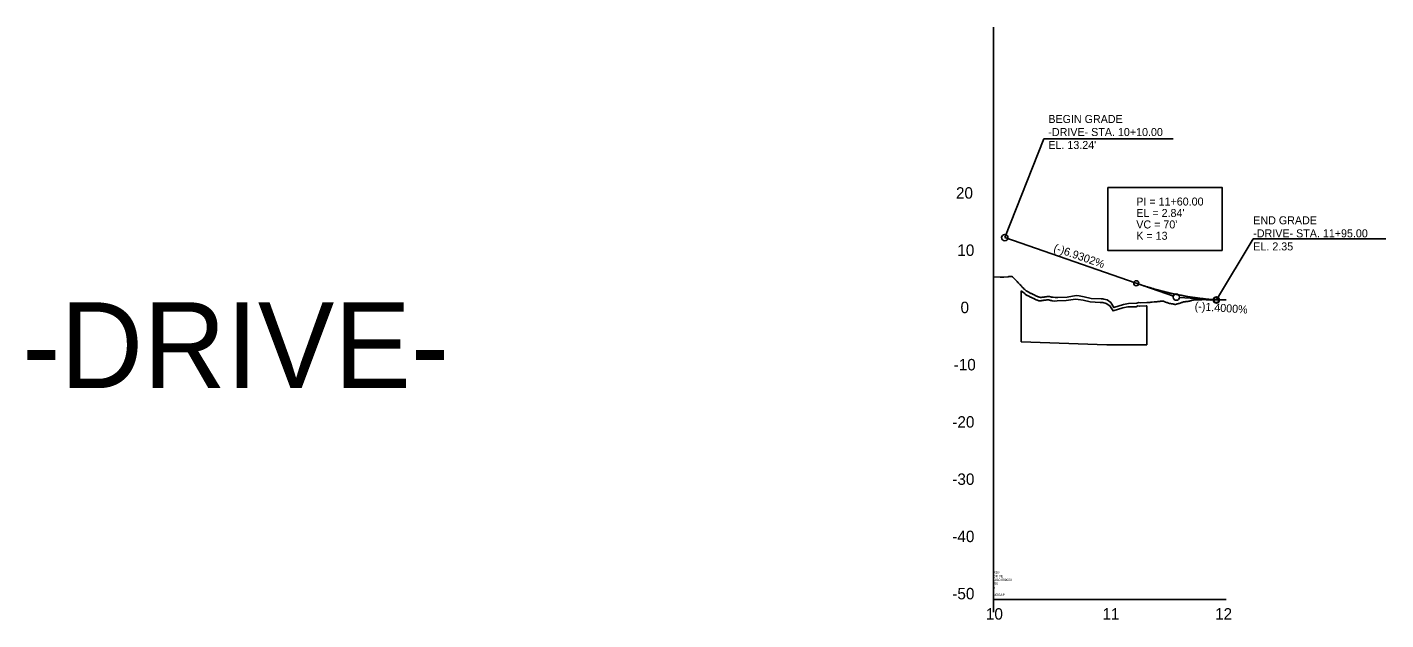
# Model space of a CAD drawing. Extents: x 1626634 to 1638383, y 876896 to 886347.
# Drawn here: x 1631869 to 1633057, y 882819 to 883336 of the extents above; entities that cross this region are included whole.
import ezdxf

# ---------------------------------------------------------------- set-up
doc = ezdxf.new("R2010")
doc.units = 0
for name, color, linetype in [('DTM Contours Minor', 7, 'Continuous'), ('Exist Profile Cell', 7, 'Continuous'), ('Exist Vertical Profile Ground Line', 7, 'Continuous'), ('Exist Vertical Profile Horizontal Axis Label Major', 7, 'Continuous'), ('Exist Vertical Profile Vertical Axis Label', 7, 'Continuous'), ('Prop Vertical Profile Curve Label', 7, 'Continuous'), ('Prop Vertical Profile Grade', 7, 'Continuous'), ('Prop Vertical Profile Grade Label', 7, 'Continuous'), ('Prop VPI Label', 7, 'Continuous'), ('Scratch_Level_3', 7, 'Continuous')]:
    doc.layers.add(name, color=color, linetype=linetype)

msp = doc.modelspace()

# ---------------------------------------------------------------- linework, layer by layer
at = {"layer": 'DTM Contours Minor'}
msp.add_line((1632713.9, 882825.5), (1632713.9, 882971.1), dxfattribs=at)
at = {"layer": 'Exist Profile Cell'}
for q in [(1632713.9, 883336.5), (1632917.4, 882836.5), (1632713.9, 882836.5)]:
    msp.add_line((1632713.9, 882836.5), q, dxfattribs=at)
at = {"layer": 'Exist Vertical Profile Ground Line'}
msp.add_lwpolyline([(1632713.9, 883118.3), (1632720, 883118.1), (1632723, 883118.1), (1632726.8, 883118.5), (1632727.3, 883118.6), (1632727.8, 883118.6), (1632728.3, 883118.7), (1632728.7, 883118.7), (1632729.2, 883118.8), (1632730.2, 883118.7), (1632730.7, 883118.3), (1632731.2, 883117.9), (1632731.7, 883117.4), (1632732.1, 883117), (1632732.7, 883116.5), (1632733.1, 883116.1), (1632733.6, 883115.5), (1632734.1, 883115), (1632734.6, 883114.4), (1632735.1, 883113.9), (1632735.5, 883113.4), (1632736, 883112.8), (1632736.5, 883112.3), (1632737, 883111.8), (1632737.5, 883111.3), (1632738, 883110.8), (1632738.5, 883110.2), (1632738.9, 883109.7), (1632739.4, 883109.2), (1632739.9, 883108.7), (1632740.9, 883107.7), (1632741.4, 883107.4), (1632741.8, 883107.1), (1632742.3, 883106.6), (1632742.7, 883106.1), (1632743.3, 883105.8), (1632743.8, 883105.5), (1632744.3, 883105.2), (1632744.8, 883105), (1632745.2, 883104.7), (1632745.7, 883104.5), (1632746.2, 883104.3), (1632746.7, 883104), (1632747.2, 883103.8), (1632747.7, 883103.6), (1632748.2, 883103.3), (1632748.7, 883103.1), (1632749.1, 883102.9), (1632749.6, 883102.6), (1632750.1, 883102.4), (1632750.6, 883102.1), (1632751.1, 883101.9), (1632751.6, 883101.6), (1632752, 883101.4), (1632753, 883101), (1632753.5, 883100.9), (1632754, 883100.7), (1632754.5, 883100.6), (1632755, 883100.5), (1632755.5, 883100.4), (1632755.9, 883100.5), (1632756.4, 883100.6), (1632757, 883100.7), (1632757.4, 883100.8), (1632757.9, 883100.8), (1632758.4, 883100.8), (1632758.8, 883100.9), (1632759.3, 883100.9), (1632759.8, 883101), (1632760.3, 883101), (1632760.8, 883101.1), (1632761.3, 883101.1), (1632761.8, 883101.2), (1632762.7, 883101.3), (1632763.2, 883101.1), (1632763.7, 883101), (1632764.2, 883100.9), (1632764.7, 883100.8), (1632765.2, 883100.7), (1632765.6, 883100.7), (1632766.1, 883100.6), (1632768, 883100.3), (1632770.4, 883100.4), (1632778.4, 883100.8), (1632786.4, 883102), (1632788.8, 883101.7), (1632793.3, 883101), (1632799.3, 883099.6), (1632808.2, 883099.1), (1632809.7, 883099.1), (1632810.5, 883098.9), (1632813.3, 883098.2), (1632816.6, 883096), (1632819.4, 883091.6), (1632827.8, 883094.2), (1632832.2, 883095.1), (1632839.5, 883095.3), (1632841, 883096), (1632842.7, 883095.7), (1632848.2, 883096), (1632850.7, 883096), (1632851.5, 883096.2), (1632852.9, 883096.3), (1632854.5, 883096.5), (1632855.1, 883096.5), (1632855.7, 883096.6), (1632856.4, 883096.6), (1632857, 883096.7), (1632857.6, 883096.8), (1632858.2, 883096.8), (1632858.9, 883096.9), (1632859.5, 883097), (1632860.1, 883097.1), (1632860.8, 883097.1), (1632861.4, 883097.2), (1632862.1, 883097.3), (1632862.7, 883097.1), (1632863.3, 883096.8), (1632863.9, 883096.6), (1632864.5, 883096.3), (1632865.2, 883096.1), (1632865.8, 883095.9), (1632866.4, 883095.7), (1632867.1, 883095.4), (1632867.8, 883095.2), (1632868.3, 883095.1), (1632868.9, 883095), (1632869.6, 883094.9), (1632870.2, 883094.8), (1632870.8, 883094.7), (1632871.5, 883094.6), (1632872.1, 883094.5), (1632872.7, 883094.4), (1632873.1, 883094.3), (1632874, 883094.6), (1632874.6, 883094.7), (1632875.2, 883094.9), (1632875.9, 883095.1), (1632876.5, 883095.2), (1632877.4, 883095.5), (1632877.8, 883095.6), (1632878.4, 883095.9), (1632879, 883096.1), (1632879.6, 883096.4), (1632880.3, 883096.6), (1632880.9, 883096.7), (1632881.5, 883096.7), (1632882.2, 883096.8), (1632882.8, 883096.8), (1632883.5, 883096.9), (1632884, 883097), (1632884.7, 883097.1), (1632885.3, 883097.2), (1632885.9, 883097.4), (1632886.6, 883097.6), (1632887.2, 883097.8), (1632887.8, 883098), (1632888.5, 883098.1), (1632889.1, 883098.2), (1632889.7, 883098.2), (1632890.3, 883098.2), (1632891, 883098.2), (1632891.6, 883098.3), (1632892.2, 883098.3), (1632892.9, 883098.3), (1632893.5, 883098.4), (1632894.1, 883098.4), (1632894.7, 883098.4), (1632895.4, 883098.4), (1632896, 883098.4), (1632896.6, 883098.5), (1632897.3, 883098.5), (1632897.9, 883098.5), (1632898.7, 883098.5), (1632899.1, 883098.5), (1632899.8, 883098.5), (1632900.4, 883098.4), (1632901, 883098.4), (1632901.7, 883098.3), (1632902.3, 883098.3), (1632902.9, 883098.2), (1632903.5, 883098.2), (1632904.4, 883098.1), (1632911.9, 883098.3), (1632917.4, 883098.2)], dxfattribs=at)
at = {"layer": 'Prop Vertical Profile Curve Label'}
for centre in [(1632838.9, 883112.8), (1632908.9, 883098.2)]:
    msp.add_circle(centre, 2.25, dxfattribs=at)
at = {"layer": 'Prop Vertical Profile Grade'}
msp.add_line((1632723.9, 883152.7), (1632838.9, 883112.8), dxfattribs=at)
msp.add_spline([(1632838.9, 883112.8), (1632840.3, 883112.3), (1632841.7, 883111.9), (1632843.1, 883111.4), (1632844.5, 883110.9), (1632845.9, 883110.5), (1632847.3, 883110), (1632848.7, 883109.6), (1632850.1, 883109.2), (1632851.5, 883108.8), (1632852.9, 883108.3), (1632854.3, 883107.9), (1632855.7, 883107.5), (1632857.1, 883107.2), (1632858.5, 883106.8), (1632859.9, 883106.4), (1632861.3, 883106), (1632862.7, 883105.7), (1632864.1, 883105.3), (1632865.5, 883105), (1632866.9, 883104.7), (1632868.3, 883104.3), (1632869.7, 883104), (1632871.1, 883103.7), (1632872.5, 883103.4), (1632873.9, 883103.1), (1632875.3, 883102.8), (1632876.7, 883102.5), (1632878.1, 883102.3), (1632879.5, 883102), (1632880.9, 883101.7), (1632882.3, 883101.5), (1632883.7, 883101.2), (1632885.1, 883101), (1632886.5, 883100.8), (1632887.9, 883100.6), (1632889.3, 883100.4), (1632890.7, 883100.2), (1632892.1, 883100), (1632893.5, 883099.8), (1632894.9, 883099.6), (1632896.3, 883099.4), (1632897.7, 883099.3), (1632899.1, 883099.1), (1632900.5, 883099), (1632901.9, 883098.8), (1632903.3, 883098.7), (1632904.7, 883098.6), (1632906.1, 883098.4), (1632907.5, 883098.3), (1632908.9, 883098.2)], degree=3, dxfattribs=at)
at = {"layer": 'Prop VPI Label'}
for p, q in [((1632723.9, 883152.7), (1632758.1, 883238.9)), ((1632871.2, 883238.9), (1632758.1, 883238.9)), ((1632908.9, 883098.2), (1632941.2, 883151.6)), ((1633057.1, 883151.6), (1632941.2, 883151.6)), ((1632838.9, 883112.8), (1632871.3, 883101.6)), ((1632908.9, 883098.2), (1632876.6, 883100.5))]:
    msp.add_line(p, q, dxfattribs=at)
msp.add_lwpolyline([(1632813.9, 883196.5), (1632913.9, 883196.5), (1632913.9, 883141.5), (1632813.9, 883141.5)], close=True, dxfattribs=at)
msp.add_lwpolyline([(1632813.9, 883196.5), (1632913.9, 883196.5), (1632913.9, 883141.5), (1632813.9, 883141.5)], close=True, dxfattribs=at)
for centre in [(1632723.9, 883152.7), (1632723.9, 883152.7), (1632873.9, 883100.7), (1632908.9, 883098.2)]:
    msp.add_circle(centre, 2.75, dxfattribs=at)
at = {"layer": 'Scratch_Level_3'}
for p, q in [((1632738.1, 883106.1), (1632738.1, 883061.5)), ((1632848.1, 883059), (1632848.1, 883093)), ((1632738.1, 883061.5), (1632813.1, 883059)), ((1632813.1, 883059), (1632848.1, 883059))]:
    msp.add_line(p, q, dxfattribs=at)
msp.add_lwpolyline([(1632738.1, 883106.1), (1632740.6, 883104.4), (1632741, 883104.1), (1632741.5, 883103.6), (1632741.9, 883103.1), (1632742.5, 883102.8), (1632743, 883102.5), (1632743.5, 883102.2), (1632744, 883102), (1632744.4, 883101.7), (1632744.9, 883101.5), (1632745.4, 883101.3), (1632745.9, 883101), (1632746.4, 883100.8), (1632746.9, 883100.6), (1632747.4, 883100.4), (1632747.9, 883100.1), (1632748.3, 883099.9), (1632748.8, 883099.6), (1632749.3, 883099.4), (1632749.8, 883099.1), (1632750.3, 883098.9), (1632750.8, 883098.7), (1632751.2, 883098.4), (1632752.2, 883098), (1632752.7, 883097.9), (1632753.2, 883097.8), (1632753.7, 883097.6), (1632754.2, 883097.5), (1632754.7, 883097.4), (1632755.1, 883097.5), (1632755.6, 883097.6), (1632756.2, 883097.7), (1632756.6, 883097.8), (1632757.1, 883097.8), (1632757.6, 883097.8), (1632758, 883097.9), (1632758.5, 883097.9), (1632759, 883098), (1632759.5, 883098), (1632760, 883098.1), (1632760.5, 883098.2), (1632761, 883098.2), (1632761.9, 883098.3), (1632762.4, 883098.2), (1632762.9, 883098), (1632763.4, 883097.9), (1632763.9, 883097.8), (1632764.4, 883097.7), (1632764.8, 883097.7), (1632765.3, 883097.6), (1632767.2, 883097.3), (1632769.6, 883097.4), (1632777.6, 883097.8), (1632785.6, 883099), (1632788, 883098.7), (1632792.5, 883098), (1632798.5, 883096.6), (1632807.4, 883096.1), (1632808.9, 883096.1), (1632809.7, 883095.9), (1632812.5, 883095.2), (1632815.8, 883093), (1632818.6, 883088.6), (1632827, 883091.2), (1632831.4, 883092.1), (1632838.7, 883092.3), (1632840.2, 883093), (1632841.9, 883092.7), (1632847.4, 883093), (1632848.1, 883093)], dxfattribs=at)

# ---------------------------------------------------------------- texts
at = {"layer": 'Exist Profile Cell'}
for s, p in [('RDY', (1632713.9, 882859.2)), ('DRIVE', (1632713.9, 882856)), ('-50', (1632713.9, 882849.5)), ('5', (1632713.9, 882846.2)), ('1000.000000', (1632713.9, 882852.7)), ('1', (1632713.9, 882843)), ('NOGAP', (1632713.9, 882839.7))]:
    msp.add_text(s, height=2, dxfattribs=at).set_placement(p)
at = {"layer": 'Exist Vertical Profile Horizontal Axis Label Major'}
for s, p in [('10', (1632707.4, 882819)), ('11', (1632809.3, 882819)), ('12', (1632907.8, 882819))]:
    msp.add_text(s, height=10, dxfattribs=at).set_placement(p)
at = {"layer": 'Exist Vertical Profile Vertical Axis Label'}
for s, p in [('20', (1632681.2, 883186.7)), ('10', (1632682.4, 883136.7)), ('0', (1632685.2, 883086.7)), ('-10', (1632679.2, 883036.7)), ('-20', (1632678, 882986.7)), ('-30', (1632678, 882936.7)), ('-40', (1632678, 882886.7)), ('-50', (1632678, 882836.7))]:
    msp.add_text(s, height=10, dxfattribs=at).set_placement(p)
at = {"layer": 'Prop Vertical Profile Curve Label'}
for s, height, p in [("VC = 70'", 7, (1632838.9, 883160.7)), ('K = 13', 7, (1632838.9, 883150.8)), ('-DRIVE-', 75, (1631864.6, 883021.2))]:
    msp.add_text(s, height=height, dxfattribs=at).set_placement(p)
at = {"layer": 'Prop Vertical Profile Grade Label'}
for s, rotation, p in [('(-)6.9302%', 340.8882, (1632766, 883141)), ('(-)1.4000%', 355.9958, (1632889.8, 883089.5))]:
    msp.add_text(s, height=7, rotation=rotation, dxfattribs=at).set_placement(p)
at = {"layer": 'Prop VPI Label'}
for s, p in [('BEGIN GRADE', (1632762, 883252.8)), ('-DRIVE- STA. 10+10.00', (1632762, 883241.4)), ("EL. 13.24'", (1632762, 883230.1)), ('PI = 11+60.00', (1632838.9, 883180.7)), ("EL = 2.84'", (1632838.9, 883170.7)), ('END GRADE', (1632941.2, 883164.3)), ('-DRIVE- STA. 11+95.00', (1632941.2, 883152.9)), ('EL. 2.35', (1632941.2, 883141.5))]:
    msp.add_text(s, height=7, dxfattribs=at).set_placement(p)

doc.saveas('drawing.dxf')
